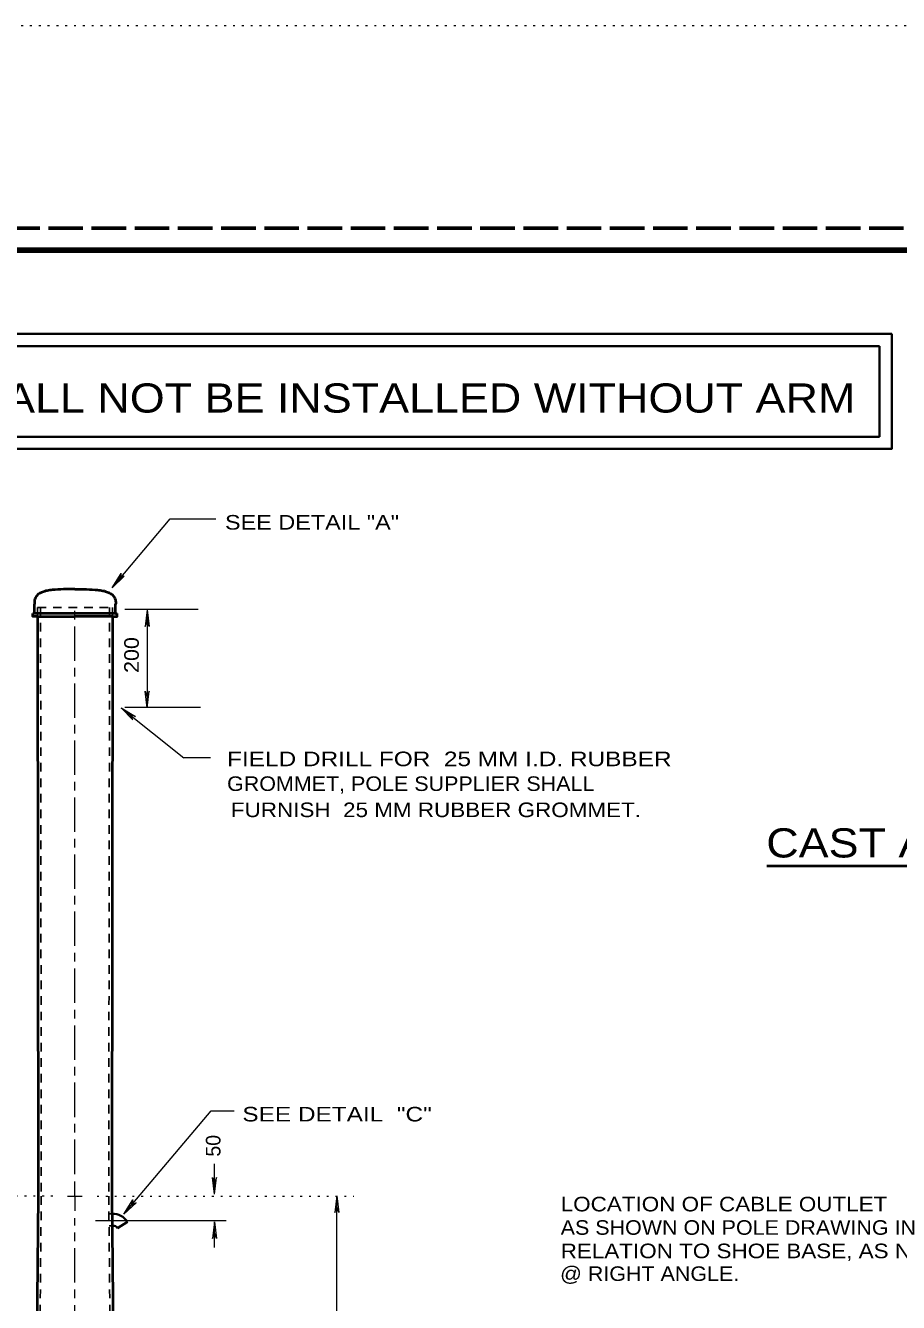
# Model space of a CAD drawing. Extents: x 312583 to 312854, y 144419 to 144597.
# Drawn here: x 312635 to 312680.5, y 144530.3 to 144596.8 of the extents above; entities that cross this region are included whole.
import ezdxf
from ezdxf.enums import TextEntityAlignment as Align

# ---------------------------------------------------------------- set-up
doc = ezdxf.new("R2010")
doc.units = 0
doc.header["$LTSCALE"] = 0.3
for name, pattern in [('DOTTED', [1.5, 0.3, -1.2]), ('LONG_DASH_SHORT_DASH', [9.9, 6, -1.2, 1.5, -1.2]), ('LONG_DASHED', [7.5, 6, -1.5]), ('SHORT_DASHED', [2.7, 1.5, -1.2])]:
    doc.linetypes.add(name, pattern=pattern)
for name, color, linetype, lineweight in [('1', 7, 'Continuous', 35), ('2', 7, 'Continuous', 13), ('62', 7, 'DOTTED', 13), ('63', 7, 'LONG_DASHED', 60)]:
    doc.layers.add(name, color=color, linetype=linetype, lineweight=lineweight)

msp = doc.modelspace()

# ---------------------------------------------------------------- linework, layer by layer
at = {"layer": '1', "lineweight": 40}
for p, q in [((312639.7037, 144566.1586), (312635.395, 144566.1586)), ((312635.4717, 144566.1586), (312635.4717, 144566.634)), ((312639.7037, 144566.1586), (312639.7037, 144566.634)), ((312639.7037, 144566.1586), (312639.788, 144566.1586)), ((312635.6327, 144565.9976), (312637.5877, 144565.9976)), ((312635.6327, 144565.9976), (312635.671, 144535.8063)), ((312639.5427, 144565.9976), (312637.5877, 144565.9976)), ((312639.5427, 144565.9976), (312639.5044, 144535.8063)), ((312635.671, 144535.8063), (312635.3874, 144507.5393)), ((312639.5044, 144535.8063), (312639.788, 144507.5393))]:
    msp.add_line(p, q, dxfattribs=at)
at = {"layer": '1', "linetype": 'SHORT_DASHED', "lineweight": 25}
for p, q in [((312635.6327, 144566.473), (312635.6327, 144565.9976)), ((312635.6327, 144566.473), (312639.5427, 144566.473)), ((312635.7937, 144566.473), (312635.832, 144535.8063)), ((312639.3894, 144566.473), (312639.3434, 144535.8063)), ((312639.5427, 144566.473), (312639.5427, 144565.9976)), ((312635.832, 144535.8063), (312635.5484, 144507.5393)), ((312639.3434, 144535.8063), (312639.6347, 144507.3553)), ((312639.5274, 144534.8786), (312639.3664, 144534.8786)), ((312639.5274, 144534.2653), (312639.3664, 144534.2653))]:
    msp.add_line(p, q, dxfattribs=at)
at = {"layer": '1', "linetype": 'LONG_DASH_SHORT_DASH', "lineweight": 13}
for p, q in [((312637.5877, 144536.9563), (312637.5877, 144566.473)), ((312637.5877, 144507.5393), (312637.5877, 144534.6563))]:
    msp.add_line(p, q, dxfattribs=at)
at = {"layer": '1', "lineweight": 13}
for p, q in [((312637.5877, 144535.8063), (312637.5877, 144536.573)), ((312637.189, 144535.8063), (312637.9557, 144535.8063)), ((312637.5877, 144535.8063), (312637.5877, 144535.0396)), ((312638.6534, 144534.5336), (312645.469, 144534.5336))]:
    msp.add_line(p, q, dxfattribs=at)
at = {"layer": '1', "linetype": 'DOTTED', "lineweight": 13}
for p, q in [((312636.4377, 144535.8063), (312625.1524, 144535.8063)), ((312638.7377, 144535.8063), (312652.1084, 144535.8063))]:
    msp.add_line(p, q, dxfattribs=at)
at = {"layer": '1'}
msp.add_line((312640.3247, 144534.4646), (312639.8034, 144534.1426), dxfattribs=at)
at = {"layer": '1', "lineweight": 158}
msp.add_lwpolyline([(312616.5, 144423.1446), (312616.5, 144585.0846), (312849, 144585.0846)], dxfattribs=at)
at = {"layer": '1', "lineweight": 40}
for points in [[(312635.6327, 144565.9976), (312635.395, 144565.9976), (312635.395, 144566.1586)], [(312639.5427, 144565.9976), (312639.788, 144565.9976), (312639.788, 144566.1586)]]:
    msp.add_lwpolyline(points, dxfattribs=at)
at = {"layer": '1'}
for radius in [0.8766, 0.2652]:
    msp.add_arc((312639.5808, 144534.0007), radius, 31.85561, 93.74313, dxfattribs=at)
at = {"layer": '1', "lineweight": 40}
for points in [[(312637.5877, 144567.4313), (312637.1354, 144567.4236), (312636.5527, 144567.393), (312636.2767, 144567.37), (312636.0007, 144567.3086), (312635.8014, 144567.232), (312635.6327, 144567.1246), (312635.51, 144566.9406), (312635.487, 144566.8486), (312635.4717, 144566.634)], [(312637.5877, 144567.4313), (312638.04, 144567.4236), (312638.6304, 144567.393), (312638.8987, 144567.37), (312639.1747, 144567.3086), (312639.374, 144567.232), (312639.5427, 144567.1246), (312639.6654, 144566.9406), (312639.696, 144566.8486), (312639.7037, 144566.634)]]:
    msp.add_spline(points, degree=3, dxfattribs=at)
at = {"layer": '2', "lineweight": 35}
for p, q in [((312621.9732, 144580.7176), (312680.1273, 144580.7176)), ((312622.6019, 144580.0889), (312679.491, 144580.0889)), ((312679.491, 144575.3549), (312679.491, 144580.0889)), ((312622.6019, 144575.3549), (312679.491, 144575.3549))]:
    msp.add_line(p, q, dxfattribs=at)
at = {"layer": '2'}
for p, q in [((312639.5197, 144567.5003), (312642.548, 144571.0806)), ((312642.548, 144571.0806), (312644.917, 144571.0806)), ((312639.5197, 144567.5003), (312639.995, 144568.2363)), ((312639.995, 144568.2363), (312639.8954, 144567.9526)), ((312639.5197, 144567.5003), (312640.156, 144568.0983)), ((312640.156, 144568.0983), (312639.8954, 144567.9526)), ((312644.0047, 144566.358), (312640.1867, 144566.358)), ((312641.352, 144566.3503), (312641.2447, 144565.484)), ((312641.352, 144566.3503), (312641.2447, 144565.484)), ((312641.352, 144566.3503), (312641.352, 144561.2366)), ((312641.352, 144566.3503), (312641.4594, 144565.484)), ((312641.352, 144566.3503), (312641.4594, 144565.484)), ((312641.2447, 144565.484), (312641.352, 144565.76)), ((312641.2447, 144565.484), (312641.352, 144565.76)), ((312641.4594, 144565.484), (312641.352, 144565.76)), ((312641.4594, 144565.484), (312641.352, 144565.76)), ((312641.2447, 144562.103), (312641.352, 144561.827)), ((312641.352, 144561.2366), (312641.2447, 144562.103)), ((312641.4594, 144562.103), (312641.352, 144561.827)), ((312641.352, 144561.2366), (312641.4594, 144562.103)), ((312639.995, 144561.2443), (312643.2527, 144558.6351)), ((312639.995, 144561.2443), (312640.6007, 144560.6156)), ((312639.995, 144561.2443), (312640.7387, 144560.7843)), ((312644.1197, 144561.252), (312640.1867, 144561.252)), ((312640.6007, 144560.6156), (312640.455, 144560.8763)), ((312640.7387, 144560.7843), (312640.455, 144560.8763)), ((312644.6458, 144558.6351), (312643.2527, 144558.6351)), ((312644.8557, 144535.9136), (312644.8557, 144537.4869)), ((312637.5877, 144535.8063), (312637.5877, 144536.573)), ((312644.7484, 144536.78), (312644.8557, 144536.504)), ((312644.8557, 144535.9136), (312644.7484, 144536.78)), ((312644.7484, 144536.78), (312644.8557, 144536.504)), ((312644.8557, 144535.9136), (312644.7484, 144536.78)), ((312644.963, 144536.78), (312644.8557, 144536.504)), ((312644.8557, 144535.9136), (312644.963, 144536.78)), ((312644.963, 144536.78), (312644.8557, 144536.504)), ((312644.8557, 144535.9136), (312644.963, 144536.78)), ((312640.1254, 144534.871), (312640.6007, 144535.607)), ((312640.6007, 144535.607), (312640.5087, 144535.3233)), ((312651.2267, 144535.8216), (312651.1194, 144534.9553)), ((312651.2267, 144441.3913), (312651.2267, 144535.8216)), ((312651.2267, 144535.8216), (312651.334, 144534.9553)), ((312640.1254, 144534.871), (312640.7694, 144535.4613)), ((312640.7694, 144535.4613), (312640.5087, 144535.3233)), ((312651.1194, 144534.9553), (312651.2267, 144535.2313)), ((312651.334, 144534.9553), (312651.2267, 144535.2313)), ((312644.8557, 144534.457), (312644.7484, 144533.5906)), ((312644.8557, 144533.1251), (312644.8557, 144534.457)), ((312644.8557, 144534.457), (312644.963, 144533.5906)), ((312644.7484, 144533.5906), (312644.8557, 144533.8666)), ((312644.963, 144533.5906), (312644.8557, 144533.8666))]:
    msp.add_line(p, q, dxfattribs=at)
at = {"layer": '2', "lineweight": 40}
msp.add_line((312673.6269, 144553.0103), (312701.3363, 144553.0103), dxfattribs=at)
at = {"layer": '2', "lineweight": 35}
msp.add_lwpolyline([(312621.9732, 144574.7262), (312680.1273, 144574.7262), (312680.1273, 144580.7176)], dxfattribs=at)
at = {"layer": '2'}
msp.add_lwpolyline([(312640.1254, 144534.871), (312644.6807, 144540.2508), (312645.8831, 144540.2508)], dxfattribs=at)
at = {"layer": '62'}
msp.add_line((312601.2, 144596.7846), (312853.5, 144596.7846), dxfattribs=at)
at = {"layer": '63'}
msp.add_line((312851.75, 144586.2246), (312583.526, 144586.2246), dxfattribs=at)

# ---------------------------------------------------------------- texts
at = {"layer": '2', "width": 1.15}
for s, p in [('POLE SHALL NOT BE INSTALLED WITHOUT ARM', (312651.0228, 144576.6219)), ('CAST ALUMINUM ALLOY', (312687.3641, 144553.4456))]:
    msp.add_text(s, height=1.52, dxfattribs=at).set_placement(p, align=Align.CENTER)
at = {"layer": '2'}
for s, width, p in [('SEE DETAIL "A"', 1.2, (312645.4, 144570.5258)), ('FIELD DRILL FOR  25 MM I.D. RUBBER', 1.25, (312645.509, 144558.2009)), ('GROMMET, POLE SUPPLIER SHALL', 1.1, (312645.5086, 144556.911)), ('FURNISH  25 MM RUBBER GROMMET.', 1.15, (312645.7076, 144555.5484)), ('SEE DETAIL  "C"', 1.25, (312646.3046, 144539.6939)), ('LOCATION OF CABLE OUTLET', 1.15, (312662.8859, 144535.0099)), ('AS SHOWN ON POLE DRAWING IN', 1.1, (312662.8859, 144533.7899)), ('RELATION TO SHOE BASE, AS NOTED', 1.15, (312662.8859, 144532.5699)), ('@ RIGHT ANGLE.', 1.1, (312662.8552, 144531.3856))]:
    msp.add_text(s, height=0.76, dxfattribs=dict(at, width=width)).set_placement(p)
at = {"layer": '2', "width": 1.1}
msp.add_text('200', height=0.76, rotation=90, dxfattribs=at).set_placement((312640.9118, 144563.0603))
at = {"layer": '2'}
msp.add_text('50', height=0.76, rotation=90, dxfattribs=at).set_placement((312645.1656, 144537.8615))

doc.saveas('drawing.dxf')
